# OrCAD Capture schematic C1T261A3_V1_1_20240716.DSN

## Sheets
1 000_Log: title: Telink-Semi; rev: V1.1; note: C1T261A3
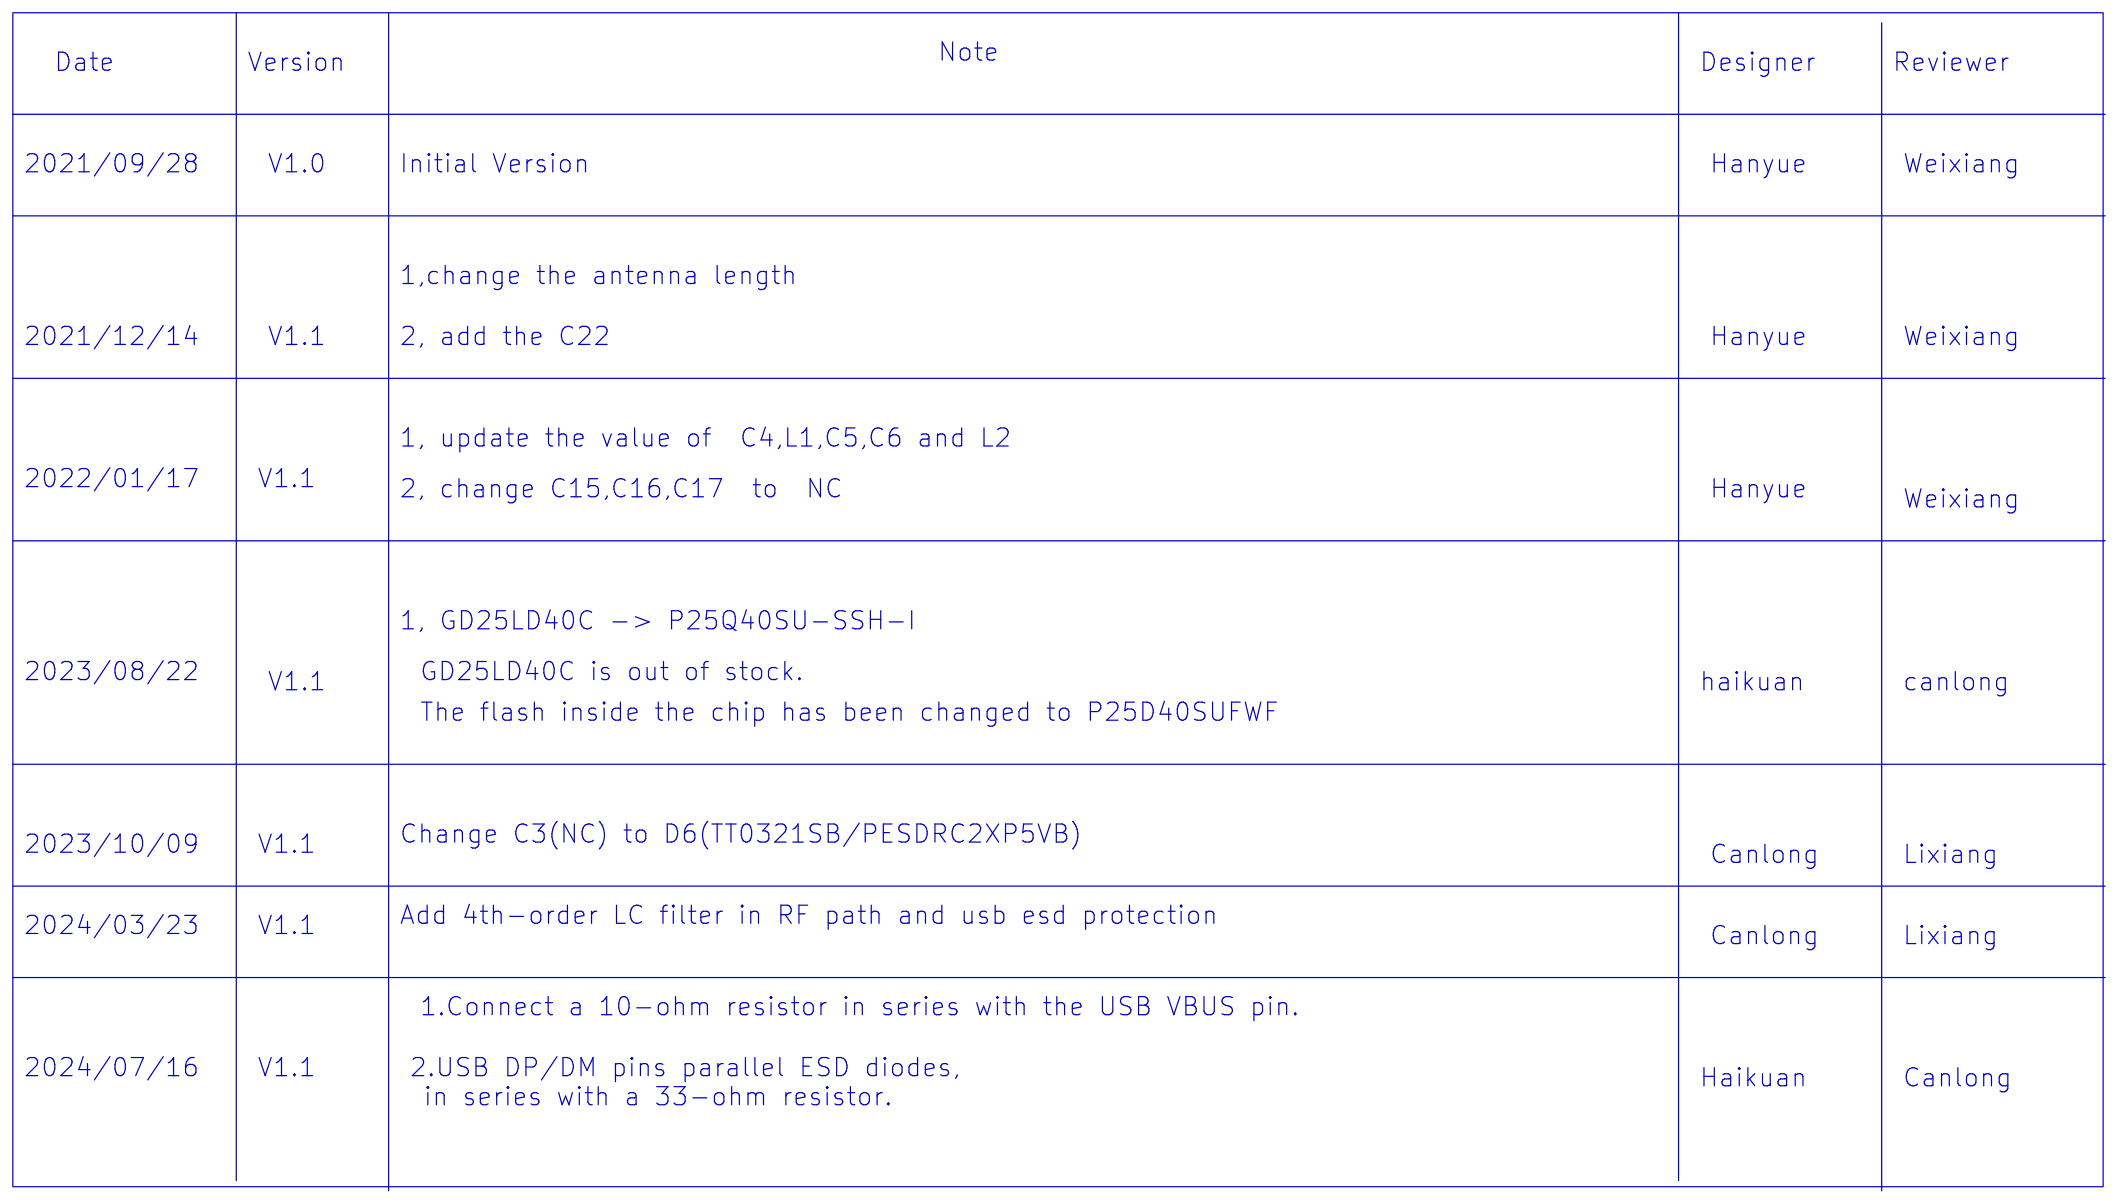
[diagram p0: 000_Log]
2 001_MCU: size A4
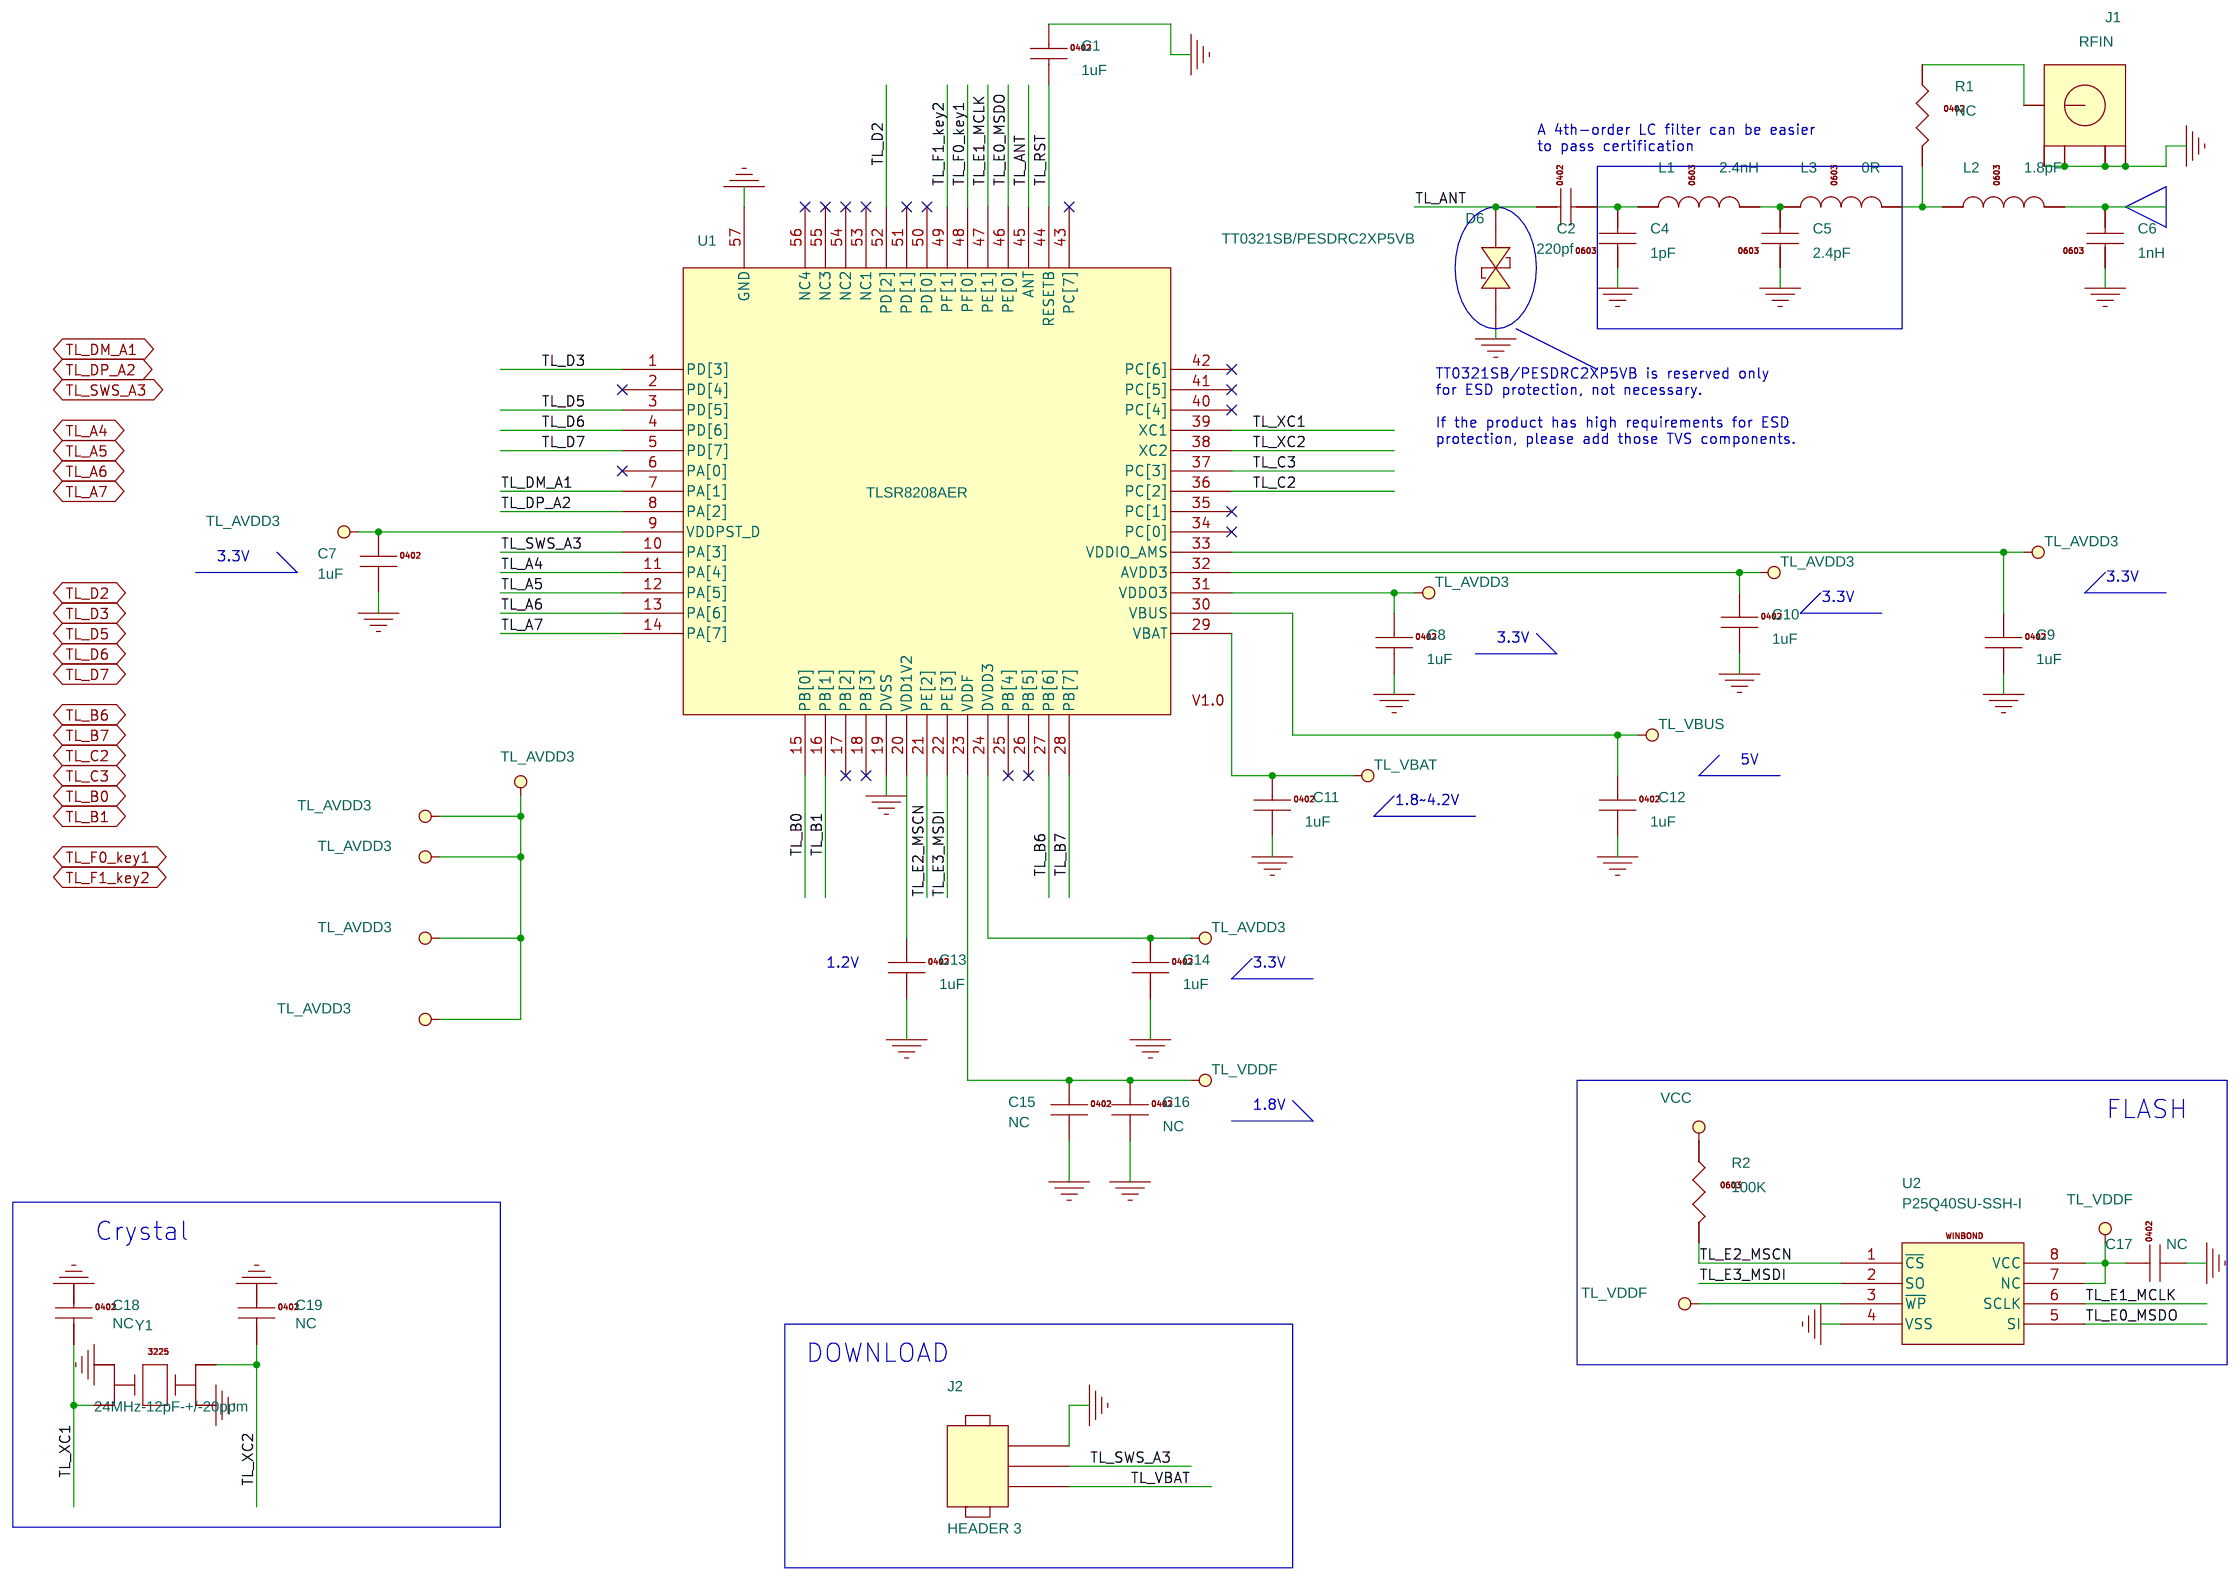
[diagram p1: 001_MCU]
3 002_POWER: size A4
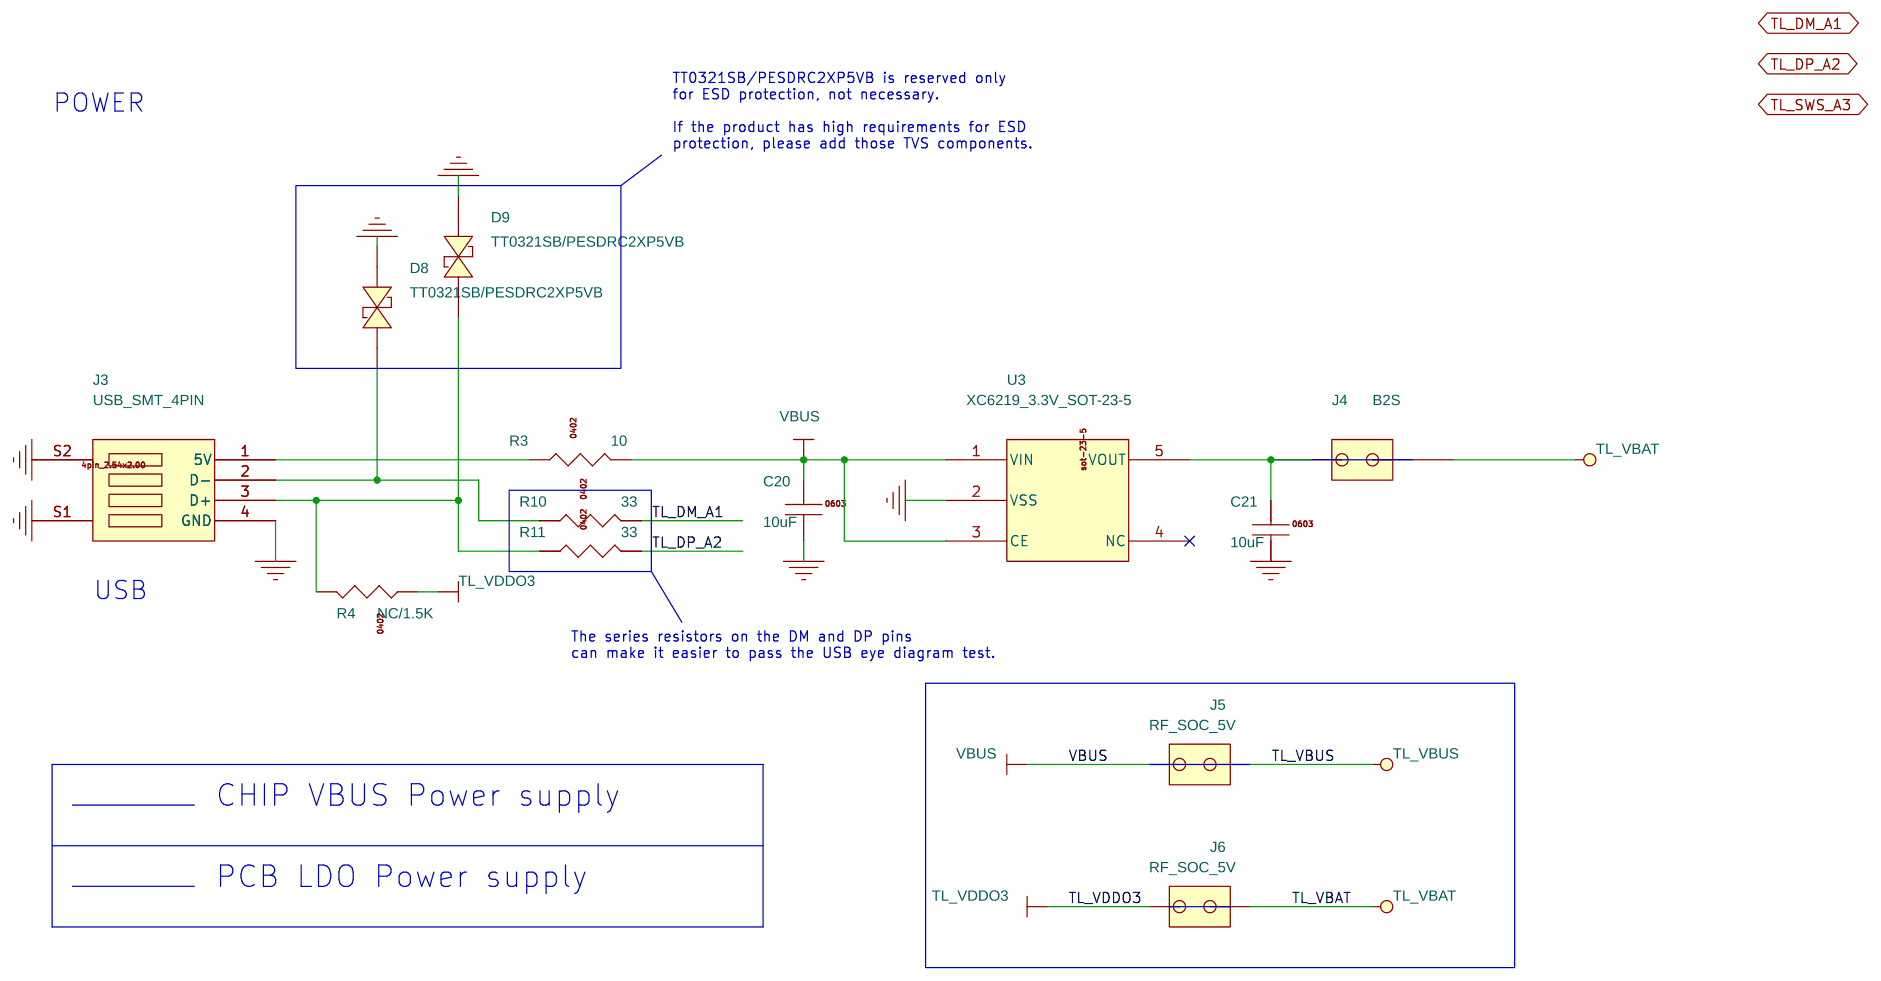
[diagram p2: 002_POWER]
4 003_INTERFACE: size A
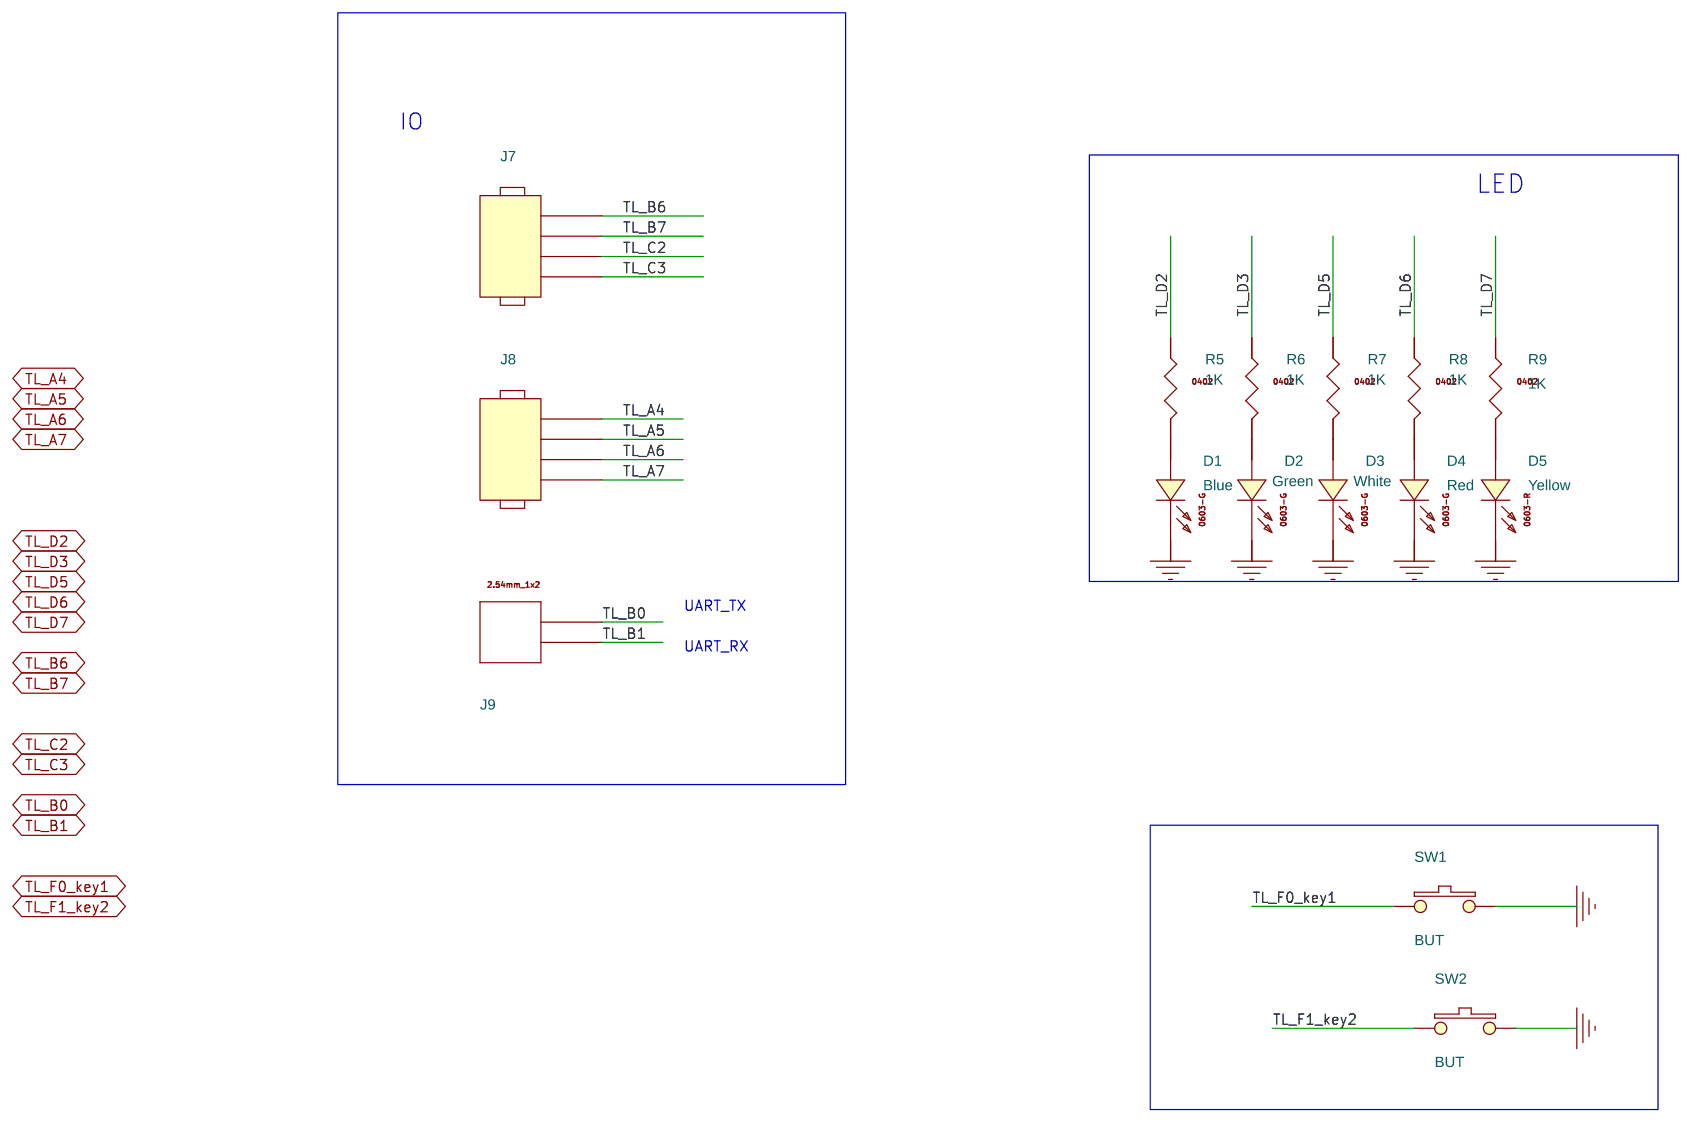
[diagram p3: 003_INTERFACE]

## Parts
sheet 001_MCU
C1  1uF  [0402]
C2  220pf  [0402]
C4  1pF  [0402]
C5  2.4pF  [0402]
C6  1nH  [0402]
C7  1uF  [0402]
C8  1uF  [0402]
C9  1uF  [0402]
C10  1uF  [0402]
C11  1uF  [0402]
C12  1uF  [0402]
C13  1uF  [0402]
C14  1uF  [0402]
C15  NC  [0402]
C16  NC  [0402]
C17  NC  [0402]
C18  NC  [0402]
C19  NC  [0402]
D6  TT0321SB/PESDRC2XP5VB  [DFN1006-2L]
J1  RFIN  [SMA-H]
J2  HEADER 3  [hdr254m-1x3]
L1  2.4nH  [0402]
L2  1.8pF  [0402]
L3  0R  [0402]
R1  NC  [0402]
R2  100K  [0402]
U1  TLSR8208AER  [qfn_7x7_56pin_0p4_4p10x4p10]
U2  P25Q40SU-SSH-I  [W25X10_20_40BL]
Y1  24MHz-12pF-+/-20ppm  [osccc200x250x080]
sheet 002_POWER
C20  10uF  [0402]
C21  10uF  [0402]
D8  TT0321SB/PESDRC2XP5VB  [DFN1006-2L]
D9  TT0321SB/PESDRC2XP5VB  [DFN1006-2L]
J3  USB_SMT_4PIN  [usb-m-4]
J4  B2S  [HDR254F-1X2X850]
J5  RF_SOC_5V  [HDR254F-1X2X850]
J6  RF_SOC_5V  [HDR254F-1X2X850]
R3  10  [0402]
R4  NC/1.5K  [0402]
R10  33  [0402]
R11  33  [0402]
U3  XC6219_3.3V_SOT-23-5  [sot-23-5]
sheet 003_INTERFACE
D1  Blue  [0603-LED]
D2  Green  [0603-LED]
D3  White  [0603-LED]
D4  Red  [0603-LED]
D5  Yellow  [0603-LED]
J7  HEADER 4  [hdr254f-1x4x850]
J8  HEADER 4  [hdr254f-1x4x850]
J9  CON_2.54mm_1x2  [hdr254f-1x2x850]
R5  1K  [0402]
R6  1K  [0402]
R7  1K  [0402]
R8  1K  [0402]
R9  1K  [0402]
SW1  BUT  [butsmd2px4_00y3_00]
SW2  BUT  [butsmd2px4_00y3_00]

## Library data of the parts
C1 C7-C17 = C1005X5R1C105K
C2 = C1005X5R1C104K
C4-C6 = C1608_NC
C18 C19 = C1005_NC
D6 D8 D9 = DIODE_SCHOTTKY_0
J1 = SMA_JACK_2: PART: RF
J2 = HEADER_3
L1-L3 = MLK1608_000R
R1 R9 = RS0402K332JT
R2 = RS0603K102JT
U1 = TLSR8208AER_3
U2 = GD25LD40C
Y1 = OSC_25x32_4pin
C20 C21 = C1608X5R0J106M
J3 = USB_SMT_1
J4 = B2S_0
J5 J6 = B2S_3: PAGE: POWER
R3 R4 R10 R11 = RS0402K100JT
U3 = XC6219_1.3V_SOT-23-5
D1-D4 = 0603D_Green
D5 = 0603D_Red
J7 J8 = HEADER_4
J9 = CON_2.54mm_1x2
R5-R8 = RS0402K102JT
SW1 SW2 = SW_PUSHBUTTON-SPST_SM: PART: FLASH

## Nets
GND: C1.1 C4.1 C5.1 C6.1 C7.2 C8.2 C9.2 C10.2 C11.2 C12.2 C13.2 C14.2 C15.2 C16.2 C17.2 C18.1 C19.1 C20.2 C21.2 D1.C(CATHODE) D2.C(CATHODE) D3.C(CATHODE) D4.C(CATHODE) D5.C(CATHODE) D6.C(CATHODE) D8.A(ANODE) D9.A(ANODE) J1.2 J1.3 J1.4 J1.5 J2.1 J3.4(GND) J3.S1 J3.S2 SW1.2 SW2.2 U1.19(DVSS) U1.57(GND) U2.4(VSS) U3.2(VSS) Y1.2 Y1.4
VBUS: C20.1 J5.1 R3.2 U3.1(VIN) U3.3(CE)
TL_A4: U1.11(PA[4])
TL_A4 (page 003_INTERFACE): J8.1
TL_A5: U1.12(PA[5])
TL_A5 (page 003_INTERFACE): J8.2
TL_A6: U1.13(PA[6])
TL_A6 (page 003_INTERFACE): J8.3
TL_A7: U1.14(PA[7])
TL_A7 (page 003_INTERFACE): J8.4
TL_ANT: C2.1 D6.A(ANODE) U1.45(ANT)
TL_AVDD3: C7.1 C8.1 C9.1 C10.1 C14.1 J6.1 R4.1 U1.9(VDDPST_D) U1.24(DVDD3) U1.31(VDDO3) U1.32(AVDD3) U1.33(VDDIO_AMS)
TL_B0: U1.15(PB[0])
TL_B0 (page 003_INTERFACE): J9.1
TL_B1: U1.16(PB[1])
TL_B1 (page 003_INTERFACE): J9.2
TL_B6: U1.27(PB[6])
TL_B6 (page 003_INTERFACE): J7.1
TL_B7: U1.28(PB[7])
TL_B7 (page 003_INTERFACE): J7.2
TL_C2: U1.36(PC[2])
TL_C2 (page 003_INTERFACE): J7.3
TL_C3: U1.37(PC[3])
TL_C3 (page 003_INTERFACE): J7.4
TL_D2: U1.52(PD[2])
TL_D2 (page 003_INTERFACE): R5.1
TL_D3: U1.1(PD[3])
TL_D3 (page 003_INTERFACE): R6.1
TL_D5: U1.3(PD[5])
TL_D5 (page 003_INTERFACE): R7.1
TL_D6: U1.4(PD[6])
TL_D6 (page 003_INTERFACE): R8.1
TL_D7: U1.5(PD[7])
TL_D7 (page 003_INTERFACE): R9.1
TL_DM_A1: U1.7(PA[1])
TL_DM_A1 (page 002_POWER): R10.2
TL_DP_A2: U1.8(PA[2])
TL_DP_A2 (page 002_POWER): R11.2
TL_E0_MSDO: U1.46(PE[0]) U2.5(SI)
TL_E1_MCLK: U1.47(PE[1]) U2.6(SCLK)
TL_E2_MSCN: R2.2 U1.21(PE[2]) U2.1(~{CS})
TL_E3_MSDI: U1.22(PE[3]) U2.2(SO)
TL_F0_key1: U1.48(PF[0])
TL_F0_key1 (page 003_INTERFACE): SW1.1
TL_F1_key2: U1.49(PF[1])
TL_F1_key2 (page 003_INTERFACE): SW2.1
TL_RST: C1.2 U1.44(RESETB)
TL_SWS_A3: J2.2 U1.10(PA[3])
TL_VBAT: C11.1 J2.3 J4.2 J6.2 U1.29(VBAT)
TL_VBUS: C12.1 J5.2 U1.30(VBUS)
TL_VDDF: C15.1 C16.1 C17.1 R2.1 U1.23(VDDF) U2.3(~{WP}) U2.7(NC) U2.8(VCC)
TL_XC1: C18.2 U1.39(XC1) Y1.1
TL_XC2: C19.2 U1.38(XC2) Y1.3
N19730495: C13.1 U1.20(VDD1V2)
N19767303: C21.1 J4.1 U3.5(VOUT)
N19767305: J3.1(5V) R3.1
N19767384: D8.C(CATHODE) J3.2(D-) R10.1
N19767387: D9.C(CATHODE) J3.3(D+) R4.2 R11.1
N19771186: C2.2 C4.2 L1.1
N19771236: C6.2 L2.2
N19784488: L2.1 L3.2 R1.2
N19784595: J1.1 R1.1
N19784974: C5.2 L1.2 L3.1
N19794289: D5.A(ANODE) R9.2
N19794293: D4.A(ANODE) R8.2
N19794296: D1.A(ANODE) R5.2
N19794298: D2.A(ANODE) R6.2
N19794300: D3.A(ANODE) R7.2

Not connected (* = marked no-connect by the designer): U1 2(PD[4])* 6(PA[0])* 17(PB[2])* 18(PB[3])* 25(PB[4])* 26(PB[5])* 34(PC[0])* 35(PC[1])* 40(PC[4])* 41(PC[5])* 42(PC[6])* 43(PC[7])* 50(PD[0])* 51(PD[1])* 53(NC1)* 54(NC2)* 55(NC3)* 56(NC4)*; U3 4(NC)*

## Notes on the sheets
sheet 1
- Date
- Version
- Note
- Designer
- Reviewer
- 2021/09/28
- V1.0
- Initial Version
- Hanyue
- Weixiang
- 1,change the antenna length
- 2021/12/14
- V1.1
- 2, add the C22
- Hanyue
- Weixiang
- 1, update the value of  C4,L1,C5,C6 and L2
- 2022/01/17
- V1.1
- 2, change C15,C16,C17  to  NC
- Hanyue
- Weixiang
- 1, GD25LD40C -> P25Q40SU-SSH-I
- 2023/08/22
- V1.1
- GD25LD40C is out of stock.
- haikuan
- canlong
- The flash inside the chip has been changed to P25D40SUFWF
- Change C3(NC) to D6(TT0321SB/PESDRC2XP5VB)
- 2023/10/09
- V1.1
- Canlong
- Lixiang
- 2024/03/23
- V1.1
- Add 4th-order LC filter in RF path and usb esd protection
- Canlong
- Lixiang
- 1.Connect a 10-ohm resistor in series with the USB VBUS pin.
- 2024/07/16
- V1.1
- 2.USB DP/DM pins parallel ESD diodes,
   in series with a 33-ohm resistor.
- Haikuan
- Canlong
sheet 2
- A 4th-order LC filter can be easier
  to pass certification
- TT0321SB/PESDRC2XP5VB is reserved only
  for ESD protection, not necessary.
  If the product has high requirements for ESD
  protection, please add those TVS components.
- 3.3V
- 3.3V
- 3.3V
- 3.3V
- 5V
- 1.8~4.2V
- 1.2V
- 3.3V
- 1.8V
- FLASH
- Crystal
- DOWNLOAD
sheet 3
- TT0321SB/PESDRC2XP5VB is reserved only
  for ESD protection, not necessary.
  If the product has high requirements for ESD
  protection, please add those TVS components.
- POWER
- USB
- The series resistors on the DM and DP pins
  can make it easier to pass the USB eye diagram test.
- CHIP VBUS Power supply
- PCB LDO Power supply
sheet 4
- IO
- LED
- UART_TX
- UART_RX
